(* Logix 5000 project; controller MyControlLogix vendor 1 type 14 code 51 rev 16.20; software revision 16.04; part 3 of 3 *)
(* tags used below, declared in another part *)
   Connection_Output : INT[248];
   MJFAULTS : DINT[12];
(* AOI56AFC, continued *)

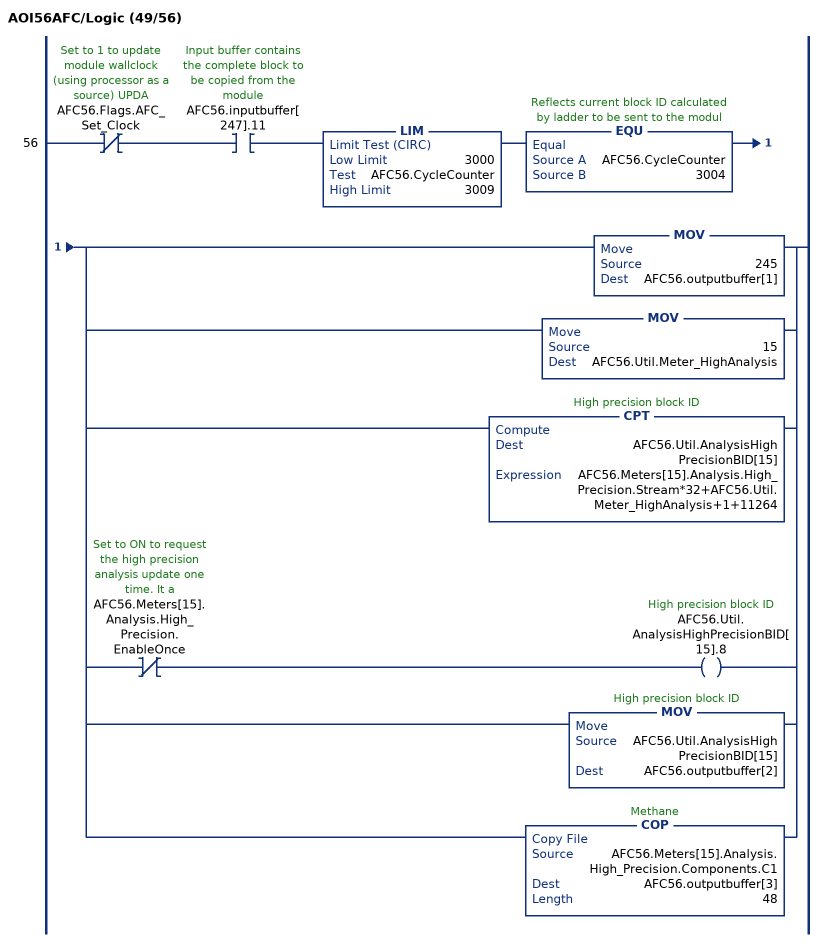
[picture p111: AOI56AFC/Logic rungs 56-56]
   56: XIO(AFC56.Flags.AFC_Set_Clock)XIC(AFC56.inputbuffer[247].11)LIM(3000,AFC56.CycleCounter,3009)EQU(AFC56.CycleCounter,3004)[MOV(245,AFC56.outputbuffer[1]) ,MOV(15,AFC56.Util.Meter_HighAnalysis) ,CPT(AFC56.Util.AnalysisHighPrecisionBID[15],AFC56.Meters[15].Analysis.High_Precision.Stream*32+AFC56.Util.Meter_HighAnalysis+1+11264) ,XIO(AFC56.Meters[15].Analysis.High_Precision.EnableOnce) OTE(AFC56.Util.AnalysisHighPrecisionBID[15].8) ,MOV(AFC56.Util.AnalysisHighPrecisionBID[15],AFC56.outputbuffer[2]) ,COP(AFC56.Meters[15].Analysis.High_Precision.Components.C1,AFC56.outputbuffer[3],48) ];
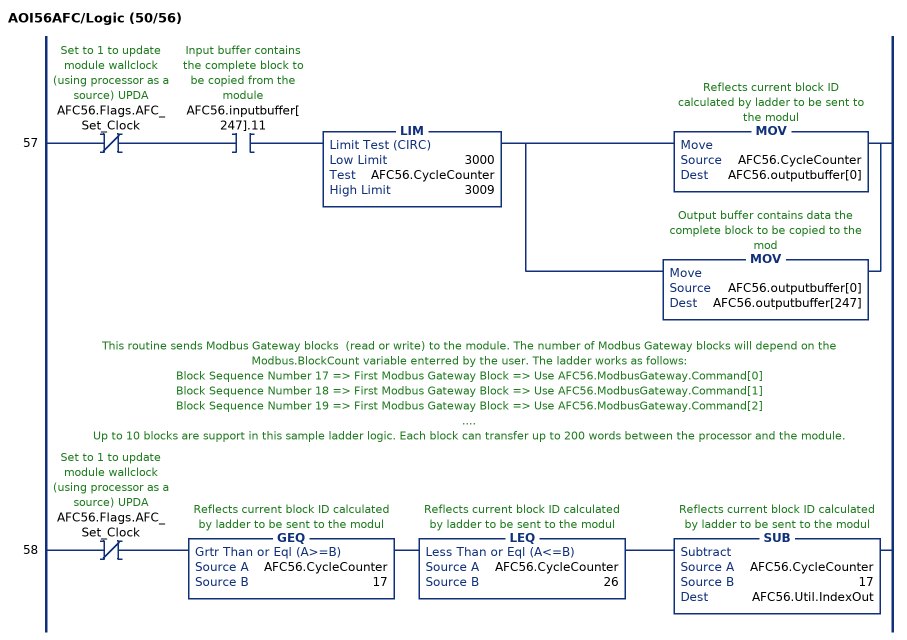
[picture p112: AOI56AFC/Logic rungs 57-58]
   57: XIO(AFC56.Flags.AFC_Set_Clock)XIC(AFC56.inputbuffer[247].11)LIM(3000,AFC56.CycleCounter,3009)[MOV(AFC56.CycleCounter,AFC56.outputbuffer[0]) ,MOV(AFC56.outputbuffer[0],AFC56.outputbuffer[247]) ];
   // This routine sends Modbus Gateway blocks  (read or write) to the module. The number of Modbus Gateway blocks will depend on the Modbus.BlockCount variable enterred by the user. The ladder works as follows:
   // Block Sequence Number 17 => First Modbus Gateway Block => Use AFC56.ModbusGateway.Command[0]
   // Block Sequence Number 18 => First Modbus Gateway Block => Use AFC56.ModbusGateway.Command[1]
   // Block Sequence Number 19 => First Modbus Gateway Block => Use AFC56.ModbusGateway.Command[2]
   // ....
   // Up to 10 blocks are support in this sample ladder logic. Each block can transfer up to 200 words between the processor and the module.
   58: XIO(AFC56.Flags.AFC_Set_Clock)GEQ(AFC56.CycleCounter,17)LEQ(AFC56.CycleCounter,26)SUB(AFC56.CycleCounter,17,AFC56.Util.IndexOut);
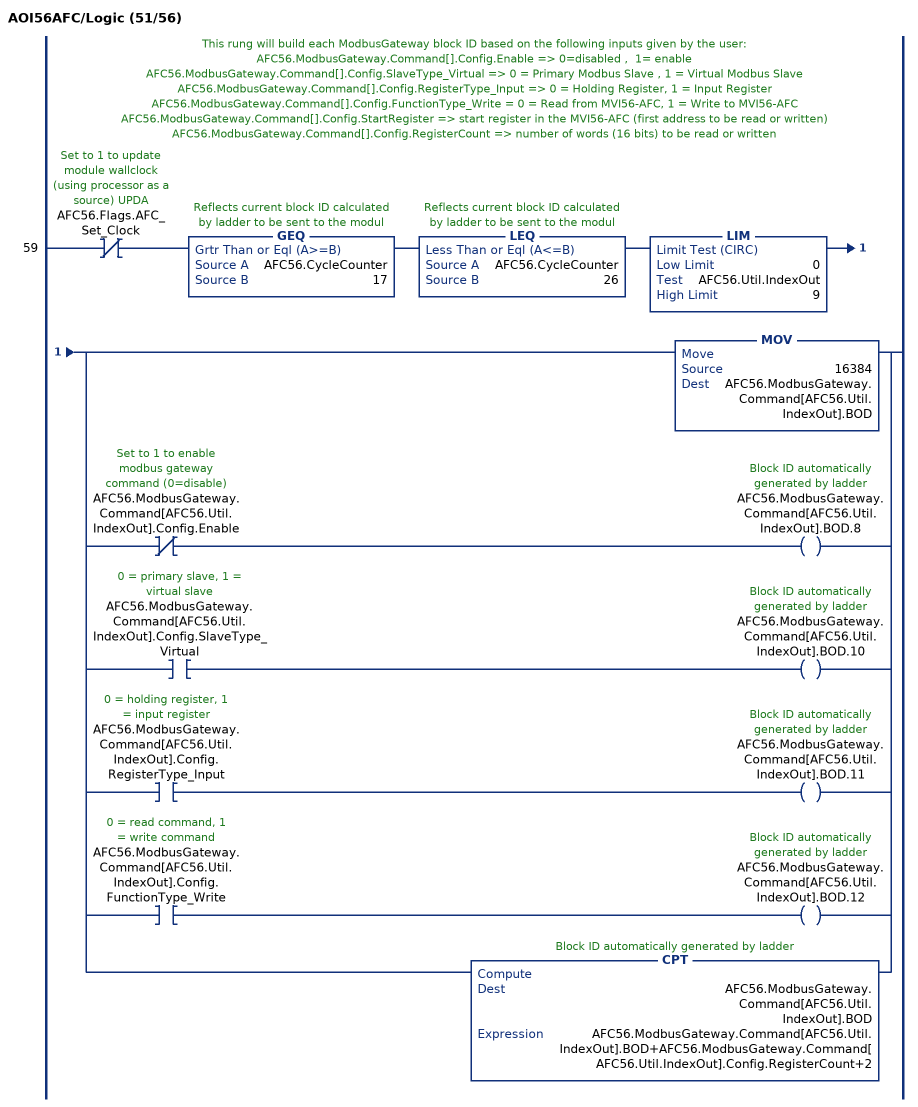
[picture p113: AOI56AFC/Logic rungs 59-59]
   // This rung will build each ModbusGateway block ID based on the following inputs given by the user:
   // AFC56.ModbusGateway.Command[].Config.Enable => 0=disabled ,  1= enable
   // AFC56.ModbusGateway.Command[].Config.SlaveType_Virtual => 0 = Primary Modbus Slave , 1 = Virtual Modbus Slave
   // AFC56.ModbusGateway.Command[].Config.RegisterType_Input => 0 = Holding Register, 1 = Input Register
   // AFC56.ModbusGateway.Command[].Config.FunctionType_Write = 0 = Read from MVI56-AFC, 1 = Write to MVI56-AFC
   // AFC56.ModbusGateway.Command[].Config.StartRegister => start register in the MVI56-AFC (first address to be read or written)
   // AFC56.ModbusGateway.Command[].Config.RegisterCount => number of words (16 bits) to be read or written
   59: XIO(AFC56.Flags.AFC_Set_Clock)GEQ(AFC56.CycleCounter,17)LEQ(AFC56.CycleCounter,26)LIM(0,AFC56.Util.IndexOut,9)[MOV(16384,AFC56.ModbusGateway.Command[AFC56.Util.IndexOut].BOD) ,XIO(AFC56.ModbusGateway.Command[AFC56.Util.IndexOut].Config.Enable) OTE(AFC56.ModbusGateway.Command[AFC56.Util.IndexOut].BOD.8) ,XIC(AFC56.ModbusGateway.Command[AFC56.Util.IndexOut].Config.SlaveType_Virtual) OTE(AFC56.ModbusGateway.Command[AFC56.Util.IndexOut].BOD.10) ,XIC(AFC56.ModbusGateway.Command[AFC56.Util.IndexOut].Config.RegisterType_Input) OTE(AFC56.ModbusGateway.Command[AFC56.Util.IndexOut].BOD.11) ,XIC(AFC56.ModbusGateway.Command[AFC56.Util.IndexOut].Config.FunctionType_Write) OTE(AFC56.ModbusGateway.Command[AFC56.Util.IndexOut].BOD.12) ,CPT(AFC56.ModbusGateway.Command[AFC56.Util.IndexOut].BOD,AFC56.ModbusGateway.Command[AFC56.Util.IndexOut].BOD+AFC56.ModbusGateway.Command[AFC56.Util.IndexOut].Config.RegisterCount+2) ];
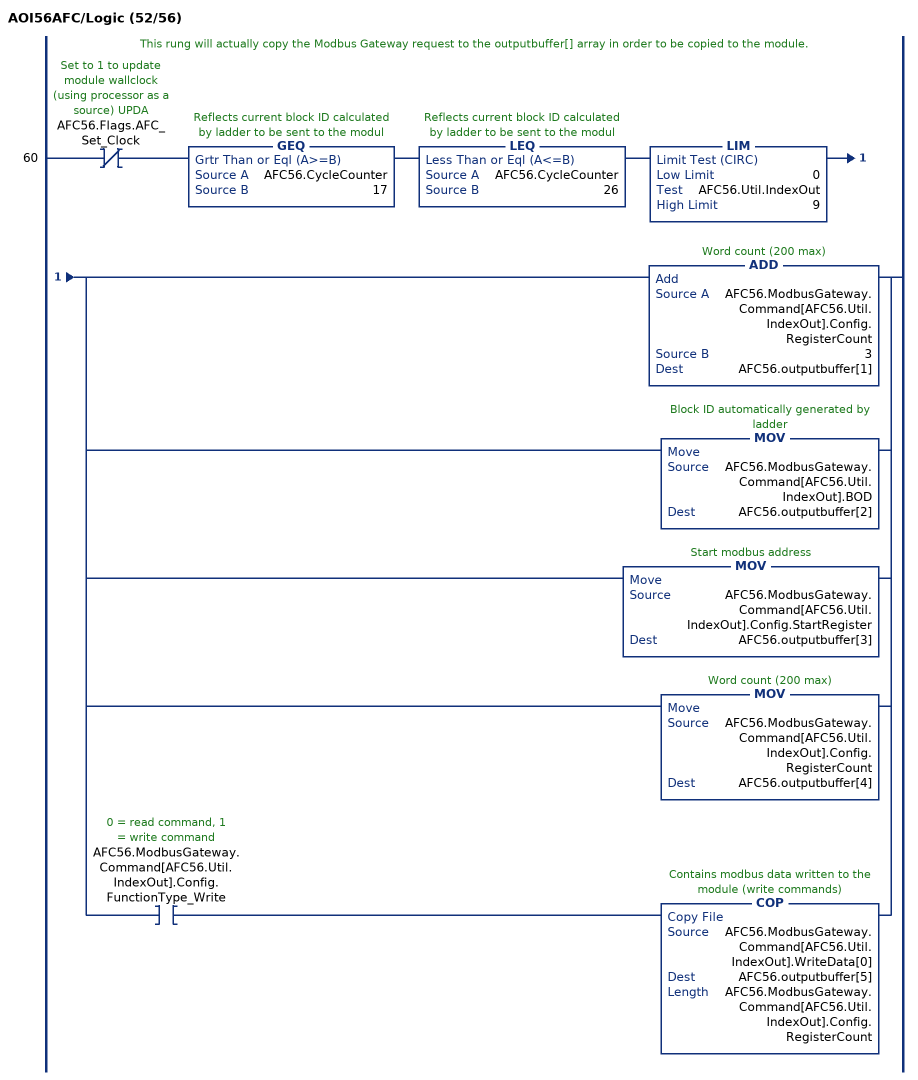
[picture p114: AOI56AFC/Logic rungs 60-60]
   // This rung will actually copy the Modbus Gateway request to the outputbuffer[] array in order to be copied to the module.
   60: XIO(AFC56.Flags.AFC_Set_Clock)GEQ(AFC56.CycleCounter,17)LEQ(AFC56.CycleCounter,26)LIM(0,AFC56.Util.IndexOut,9)[ADD(AFC56.ModbusGateway.Command[AFC56.Util.IndexOut].Config.RegisterCount,3,AFC56.outputbuffer[1]) ,MOV(AFC56.ModbusGateway.Command[AFC56.Util.IndexOut].BOD,AFC56.outputbuffer[2]) ,MOV(AFC56.ModbusGateway.Command[AFC56.Util.IndexOut].Config.StartRegister,AFC56.outputbuffer[3]) ,MOV(AFC56.ModbusGateway.Command[AFC56.Util.IndexOut].Config.RegisterCount,AFC56.outputbuffer[4]) ,XIC(AFC56.ModbusGateway.Command[AFC56.Util.IndexOut].Config.FunctionType_Write) COP(AFC56.ModbusGateway.Command[AFC56.Util.IndexOut].WriteData[0],AFC56.outputbuffer[5],AFC56.ModbusGateway.Command[AFC56.Util.IndexOut].Config.RegisterCount) ];
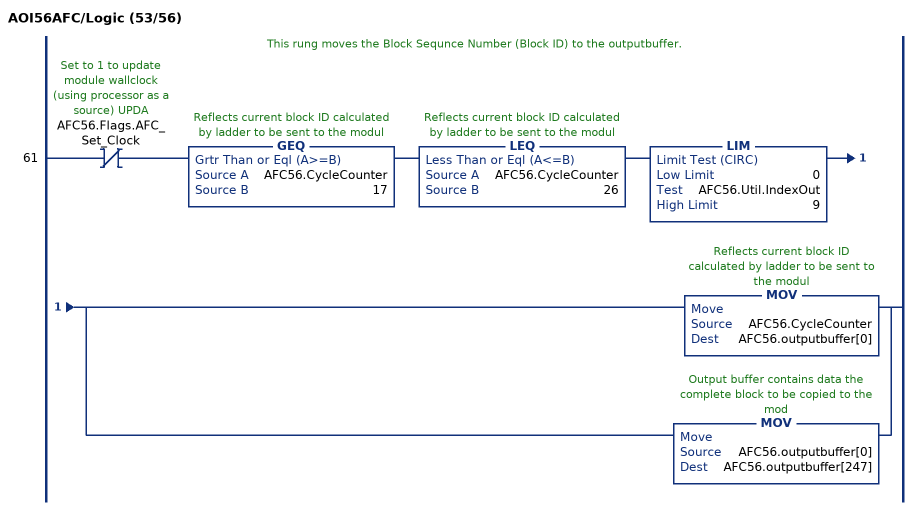
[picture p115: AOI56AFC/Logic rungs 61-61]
   // This rung moves the Block Sequnce Number (Block ID) to the outputbuffer.
   61: XIO(AFC56.Flags.AFC_Set_Clock)GEQ(AFC56.CycleCounter,17)LEQ(AFC56.CycleCounter,26)LIM(0,AFC56.Util.IndexOut,9)[MOV(AFC56.CycleCounter,AFC56.outputbuffer[0]) ,MOV(AFC56.outputbuffer[0],AFC56.outputbuffer[247]) ];
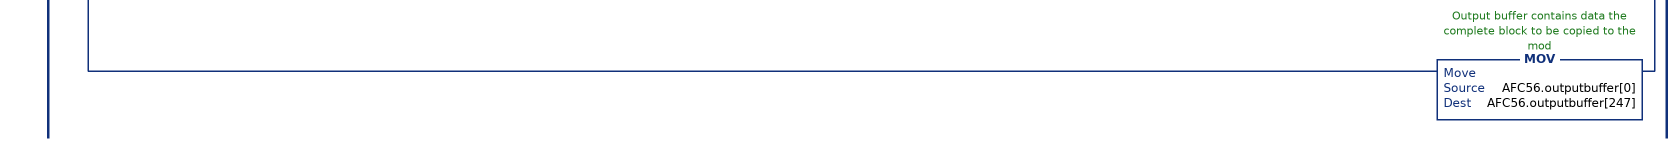
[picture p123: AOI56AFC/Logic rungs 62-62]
   // The reason to check NEQ outputbuffer[0] 5000 is to guarantee the routine will be updated one time only, so the signals can be cleared correctly once the input block is received
   62: XIO(AFC56.Flags.AFC_Set_Clock)XIC(AFC56.Prove.Input.Prove_Enabled)EQU(AFC56.CycleCounter,5000)NEQ(AFC56.outputbuffer[0],5000)[MOV(24,AFC56.outputbuffer[1]) ,MOV(16#7C00,AFC56.outputbuffer[2]) ,MOV(0,AFC56.Util.Prover_Phase) ,XIC(AFC56.Prove.Output.Process.Sequencing.Phase.Not_Selected) [OTU(AFC56.Util.Prover_Phase.0) ,OTU(AFC56.Util.Prover_Phase.1) ,OTU(AFC56.Util.Prover_Phase.2) ] ,XIC(AFC56.Prove.Output.Process.Sequencing.Phase.Active) [OTL(AFC56.Util.Prover_Phase.0) ,OTU(AFC56.Util.Prover_Phase.1) ,OTU(AFC56.Util.Prover_Phase.2) ] ,XIC(AFC56.Prove.Output.Process.Sequencing.Phase.Counting_Past_1st_Switch) [OTU(AFC56.Util.Prover_Phase.0) ,OTL(AFC56.Util.Prover_Phase.1) ,OTU(AFC56.Util.Prover_Phase.2) ] ,XIC(AFC56.Prove.Output.Process.Sequencing.Phase.Past_2nd_Switch_Fwd_Leg) [OTL(AFC56.Util.Prover_Phase.0) ,OTL(AFC56.Util.Prover_Phase.1) ,OTU(AFC56.Util.Prover_Phase.2) ] ,XIC(AFC56.Prove.Output.Process.Sequencing.Phase.Past_1st_Swith_Ret_Leg) [OTU(AFC56.Util.Prover_Phase.0) ,OTU(AFC56.Util.Prover_Phase.1) ,OTL(AFC56.Util.Prover_Phase.2) ] ,XIC(AFC56.Prove.Output.Process.Sequencing.Phase.Run_Complete) [OTL(AFC56.Util.Prover_Phase.0) ,OTU(AFC56.Util.Prover_Phase.1) ,OTL(AFC56.Util.Prover_Phase.2) ] ,NEQ(AFC56.Util.Prover_Phase,1) NEQ(AFC56.Util.Prover_Phase,2) NEQ(AFC56.Util.Prover_Phase,3) NEQ(AFC56.Util.Prover_Phase,4) NEQ(AFC56.Util.Prover_Phase,5) [OTL(AFC56.Prove.Output.Process.Sequencing.Phase.Not_Selected) ,OTU(AFC56.Prove.Output.Process.Sequencing.Phase.Active) ,OTU(AFC56.Prove.Output.Process.Sequencing.Phase.Counting_Past_1st_Switch) ,OTU(AFC56.Prove.Output.Process.Sequencing.Phase.Past_2nd_Switch_Fwd_Leg) ,OTU(AFC56.Prove.Output.Process.Sequencing.Phase.Past_1st_Swith_Ret_Leg) ,OTU(AFC56.Prove.Output.Process.Sequencing.Phase.Run_Complete) ,MOV(0,AFC56.Util.Prover_Phase) ] ,XIC(AFC56.Prove.Output.Process.Sequencing.Ball_position_ready) OTL(AFC56.Util.Prover_Phase.8) ,XIC(AFC56.Prove.Output.Process.Sequencing.Ball_Position_Sealed) OTL(AFC56.Util.Prover_Phase.9) ,XIC(AFC56.Prove.Output.Process.Sequencing.Ball_position_ready_bwd_leg) OTL(AFC56.Util.Prover_Phase.10) ,XIC(AFC56.Prove.Output.Process.Sequencing.Ball_Position_Sealed_Bwd_Leg) OTL(AFC56.Util.Prover_Phase.11) ,MOV(AFC56.Util.Prover_Phase,AFC56.outputbuffer[3]) ,COP(AFC56.Prove.Output.Process.Temperature,AFC56.outputbuffer[4],2) ,COP(AFC56.Prove.Output.Process.Outlet_Temperature,AFC56.outputbuffer[6],2) ,COP(AFC56.Prove.Output.Process.Switch_bar_temperature,AFC56.outputbuffer[8],2) ,COP(AFC56.Prove.Output.Process.Pressure,AFC56.outputbuffer[10],2) ,COP(AFC56.Prove.Output.Process.Outlet_Pressure,AFC56.outputbuffer[12],2) ,COP(AFC56.Prove.Output.Process.Prover_Density,AFC56.outputbuffer[14],2) ,MOV(0,AFC56.Util.Prover_Signals) ,XIC(AFC56.Prove.Output.Signals.EnableProve) OTL(AFC56.Util.Prover_Signals.1) ,XIC(AFC56.Prove.Output.Signals.AcceptProve) OTL(AFC56.Util.Prover_Signals.2) ,XIC(AFC56.Prove.Output.Signals.RejectProve) OTL(AFC56.Util.Prover_Signals.3) ,XIC(AFC56.Prove.Output.Signals.RunStart) OTL(AFC56.Util.Prover_Signals.4) ,XIC(AFC56.Prove.Output.Signals.RunComplete) OTL(AFC56.Util.Prover_Signals.5) ,XIC(AFC56.Prove.Output.Signals.RunCancel) OTL(AFC56.Util.Prover_Signals.6) ,XIC(AFC56.Prove.Output.Signals.RunDelete) OTL(AFC56.Util.Prover_Signals.7) ,XIC(AFC56.Prove.Output.Signals.PassComplete) OTL(AFC56.Util.Prover_Signals.9) ,XIC(AFC56.Prove.Output.Signals.PauseProve) OTL(AFC56.Util.Prover_Signals.12) ,XIC(AFC56.Prove.Output.Signals.AbortProve) OTL(AFC56.Util.Prover_Signals.14) ,MOV(AFC56.Util.Prover_Signals,AFC56.outputbuffer[16]) ,[MOV(0,AFC56.Util.Prover_Controls) ,XIC(AFC56.Prove.Output.Config.Enable.Auto_Accept_Prove) OTL(AFC56.Util.Prover_Controls.0) ,XIC(AFC56.Prove.Output.Config.Enable.Auto_Continue_Prove) OTL(AFC56.Util.Prover_Controls.1) ,XIC(AFC56.Prove.Output.Config.Accept.Apply_MF_Change_All_Streams) OTL(AFC56.Util.Prover_Controls.13) ,XIC(AFC56.Prove.Output.Config.Accept.Apply_MF_Change_Curve) OTL(AFC56.Util.Prover_Controls.14) ,XIC(AFC56.Prove.Output.Config.Accept.Apply_New_MF) OTL(AFC56.Util.Prover_Controls.15) ,MOV(AFC56.Util.Prover_Controls,AFC56.outputbuffer[17]) ,MOV(AFC56.Prove.Output.Config.Enable.Meter_Number,AFC56.outputbuffer[18]) ,MOV(AFC56.Prove.Output.Config.Accept.Requested_Interpolation_Point,AFC56.outputbuffer[21]) ] ,[COP(AFC56.Prove.Output.Pulse_Counts.Meter,AFC56.outputbuffer[22],2) ,COP(AFC56.Prove.Output.Pulse_Counts.Master_Meter,AFC56.outputbuffer[24],2) ] ,[MOV(AFC56.CycleCounter,AFC56.outputbuffer[0]) ,MOV(AFC56.outputbuffer[0],AFC56.outputbuffer[247]) ] ];
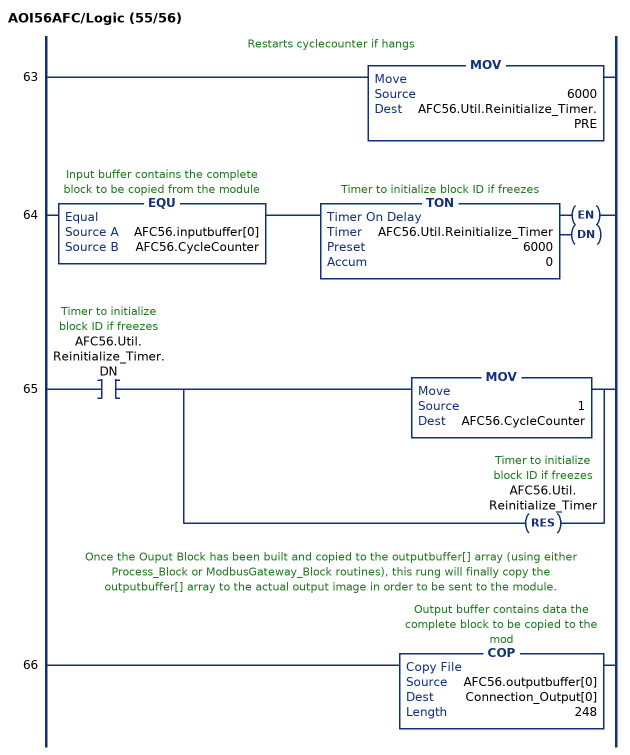
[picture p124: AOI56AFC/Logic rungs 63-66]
   // Restarts cyclecounter if hangs
   63: MOV(6000,AFC56.Util.Reinitialize_Timer.PRE);
   64: EQU(AFC56.inputbuffer[0],AFC56.CycleCounter)TON(AFC56.Util.Reinitialize_Timer,6000,0);
   65: XIC(AFC56.Util.Reinitialize_Timer.DN)[MOV(1,AFC56.CycleCounter) ,RES(AFC56.Util.Reinitialize_Timer) ];
   // Once the Ouput Block has been built and copied to the outputbuffer[] array (using either Process_Block or ModbusGateway_Block routines), this rung will finally copy the outputbuffer[] array to the actual output image in order to be sent to the module.
   66: COP(AFC56.outputbuffer[0],Connection_Output[0],248);
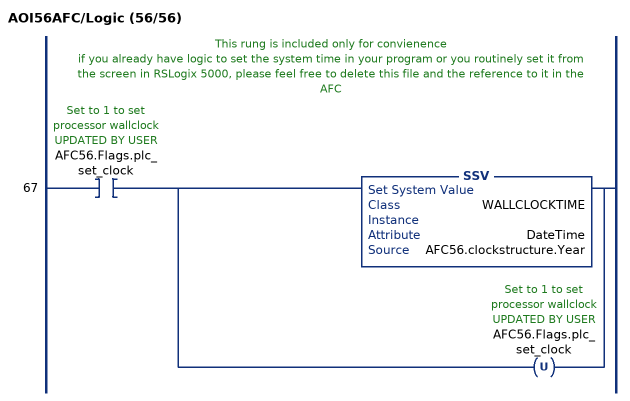
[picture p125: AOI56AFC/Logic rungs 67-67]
   // This rung is included only for convienence
   // if you already have logic to set the system time in your program or you routinely set it from the screen in RSLogix 5000, please feel free to delete this file and the reference to it in the AFC
   67: XIC(AFC56.Flags.plc_set_clock)[SSV(WALLCLOCKTIME,,DateTime,AFC56.clockstructure.Year) ,OTU(AFC56.Flags.plc_set_clock) ];
END_ROUTINE

ROUTINE Prescan   (* ladder *)
// Power Up Handler
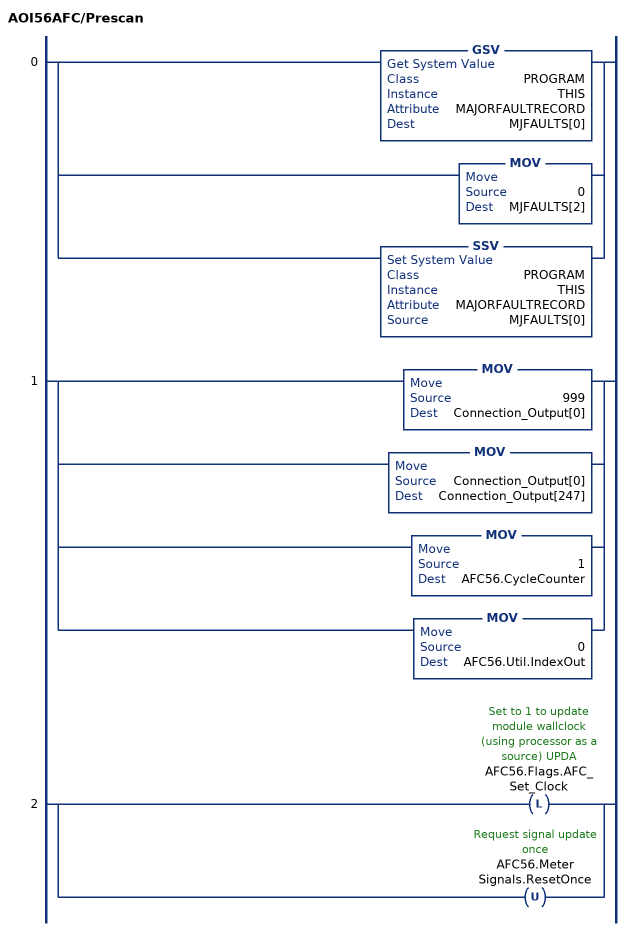
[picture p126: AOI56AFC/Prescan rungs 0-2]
   0: [GSV(PROGRAM,THIS,MAJORFAULTRECORD,MJFAULTS[0]) ,MOV(0,MJFAULTS[2]) ,SSV(PROGRAM,THIS,MAJORFAULTRECORD,MJFAULTS[0]) ];
   1: [MOV(999,Connection_Output[0]) ,MOV(Connection_Output[0],Connection_Output[247]) ,MOV(1,AFC56.CycleCounter) ,MOV(0,AFC56.Util.IndexOut) ];
   2: [OTL(AFC56.Flags.AFC_Set_Clock) ,OTU(AFC56.MeterSignals.ResetOnce) ];
END_ROUTINE
END_ADD_ON_INSTRUCTION

VAR_GLOBAL   (* controller tags *)
   AFC56 : AFC;
   AOI56AFC : AOI56AFC;
END_VAR

PROGRAM MainProgram   (* main routine MainRoutine *)

ROUTINE MainRoutine   (* ladder *)
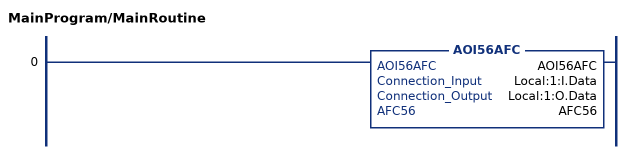
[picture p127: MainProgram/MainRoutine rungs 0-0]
   0: AOI56AFC(AOI56AFC,Local:1:I.Data,Local:1:O.Data,AFC56);
END_ROUTINE
END_PROGRAM
